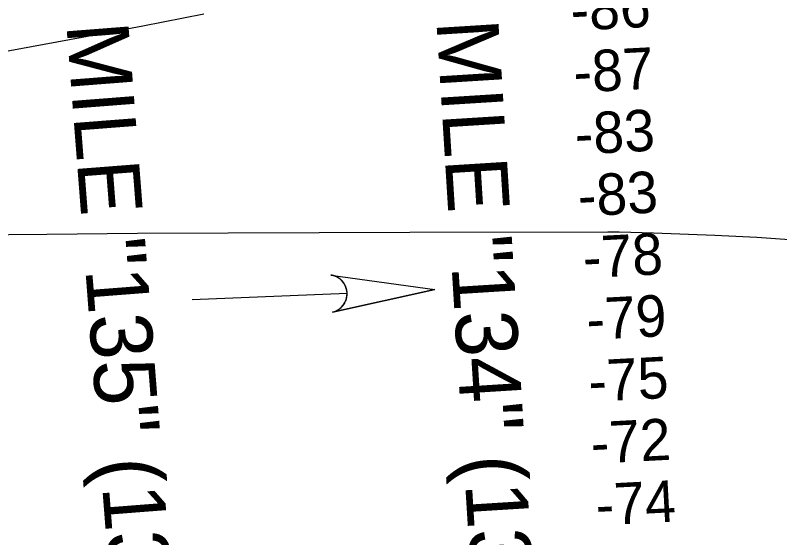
# Model space of a CAD drawing. Extents: x 3540316 to 3578335, y 553172 to 578787.
# Drawn here: x 3544891 to 3546126, y 565131 to 565975 of the extents above; entities that cross this region are included whole.
import ezdxf

# ---------------------------------------------------------------- set-up
doc = ezdxf.new("R2010")
doc.units = 0
for name, color, linetype in [('V-CHAN-NAID', 7, 'Continuous'), ('V-RIVR-RANG', 7, 'Continuous'), ('V-STRM-FLOW', 7, 'Continuous'), ('V-TOPO-MINR', 7, 'Continuous')]:
    doc.layers.add(name, color=color, linetype=linetype)

msp = doc.modelspace()

# ---------------------------------------------------------------- linework, layer by layer
at = {"layer": 'V-STRM-FLOW'}
for p, q in [((3545400.5, 565555.6), (3545568.2, 565532.5)), ((3545403, 565495.6), (3545568.2, 565532.5)), ((3545176.5, 565516.2), (3545426.7, 565526.6))]:
    msp.add_line(p, q, dxfattribs=at)
msp.add_lwpolyline([(3545400.5, 565555.6), (3545568.2, 565532.5), (3545403, 565495.6), (3545405.9, 565496.4), (3545408.6, 565497.5), (3545409.7, 565498), (3545410.6, 565498.5), (3545411.7, 565499.1), (3545412.8, 565499.7), (3545413.7, 565500.3), (3545414.8, 565501.2), (3545416, 565502.2), (3545416.7, 565502.7), (3545417.5, 565503.5), (3545418.5, 565504.6), (3545419.3, 565505.4), (3545420.1, 565506.4), (3545420.6, 565507), (3545421.1, 565507.7), (3545421.7, 565508.6), (3545422.3, 565509.5), (3545422.8, 565510.3), (3545423.2, 565511.1), (3545423.7, 565512.2), (3545424.2, 565513.2), (3545424.6, 565514.1), (3545425, 565515.1), (3545425.3, 565516), (3545425.5, 565516.8), (3545425.7, 565517.5), (3545425.9, 565518.4), (3545426.2, 565519.4), (3545426.3, 565520.4), (3545426.5, 565521.4), (3545426.6, 565522.3), (3545426.7, 565523.3), (3545426.7, 565524.1), (3545426.7, 565525.3), (3545426.7, 565526.6), (3545426.7, 565527.1), (3545426.6, 565527.7), (3545426.6, 565528.4), (3545426.5, 565529.1), (3545426.4, 565529.8), (3545426.3, 565530.5), (3545426.2, 565531.2), (3545426.1, 565531.8), (3545425.9, 565532.6), (3545425.7, 565533.3), (3545425.5, 565533.8), (3545425.1, 565535.1), (3545424.9, 565535.8), (3545424.7, 565536.2), (3545424.4, 565537), (3545424.1, 565537.7), (3545423.8, 565538.4), (3545423.4, 565539.2), (3545423, 565539.9), (3545422.7, 565540.5), (3545422.4, 565541), (3545422, 565541.6), (3545421.7, 565542.2), (3545421.2, 565542.9), (3545420.8, 565543.5), (3545420.3, 565544.2), (3545419.6, 565545), (3545419.1, 565545.5), (3545418.6, 565546.1), (3545418, 565546.7), (3545417.6, 565547.2), (3545417.1, 565547.7), (3545416.3, 565548.4), (3545416.3, 565548.4), (3545415.8, 565548.8), (3545415.4, 565549.1), (3545414.9, 565549.5), (3545414.2, 565550), (3545413.6, 565550.4), (3545413.1, 565550.8), (3545412.5, 565551.2), (3545411.8, 565551.6), (3545411.4, 565551.9), (3545410.7, 565552.2), (3545409.9, 565552.6), (3545409.4, 565552.9), (3545408.9, 565553.1), (3545408.6, 565553.3), (3545408.1, 565553.5), (3545407.5, 565553.7), (3545406.9, 565553.9), (3545406.3, 565554.2), (3545405.7, 565554.4), (3545404.9, 565554.6), (3545404.4, 565554.8), (3545403.6, 565555), (3545402.7, 565555.2), (3545402.1, 565555.3), (3545401.5, 565555.4), (3545401.1, 565555.5), (3545400.7, 565555.5)], close=True, dxfattribs=at)
msp.add_arc((3545396.2, 565525.4), 30.5, 282.7745, 81.9968, dxfattribs=at)
at = {"layer": 'V-TOPO-MINR'}
for points in [[(3544641.7, 565874.2), (3544998.4, 565939.6), (3545096.8, 565958.1), (3545195.1, 565977.3)], [(3546156.5, 565611.4), (3546088.8, 565616.3), (3546020.9, 565619.7), (3545921.7, 565623.4), (3545903.3, 565623.9), (3545884.9, 565624.4), (3545866.5, 565624.6), (3545848.2, 565624.7), (3545527.9, 565624.3), (3545381.4, 565624), (3545234.8, 565623.4), (3545088.3, 565622.5), (3544941.7, 565621.3), (3544696.3, 565619.1), (3544672.5, 565619.1), (3544648.7, 565619.2), (3544624.9, 565619.7), (3544601.1, 565620.4), (3544468.2, 565625.1)]]:
    msp.add_lwpolyline(points, dxfattribs=at)

# ---------------------------------------------------------------- texts
at = {"layer": 'V-CHAN-NAID'}
for s, rotation, p in [('MILE "134" (134.2)', 273.5663, (3545570.9, 565965.7)), ('MILE "135" (134.3)', 274.4445, (3544973, 565960.2))]:
    msp.add_text(s, height=100, rotation=rotation, dxfattribs=at).set_placement(p)
at = {"layer": 'V-RIVR-RANG'}
for s, p in [('-86', (3545789.3, 565949.9)), ('-87', (3545794, 565850)), ('-83', (3545796.1, 565750)), ('-83', (3545801.1, 565650.1)), ('-78', (3545809.2, 565550.4)), ('-79', (3545815, 565450.6)), ('-75', (3545818.1, 565350.6)), ('-72', (3545822, 565250.7)), ('-74', (3545829.9, 565150.9))]:
    msp.add_text(s, height=67, rotation=2.9898, dxfattribs=at).set_placement(p)

doc.saveas('drawing.dxf')
